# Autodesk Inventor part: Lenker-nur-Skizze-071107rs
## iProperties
Manager: Dr.-Ing. Roland Schröder
Company: www.Das-Entwicklungsbuero.de
Created: 2007-11
Part Number: Lenker-nur-Skizze-071107rs
Project: 11308
Document SubType Name: Modeling
Designer: rsc
Engineer: Dr.-Ing. Roland Schröder
Oberflächen: Ra 6,4
Toleranzen: ISO 2768 - m
Kanten: brechen
Author: rsc
